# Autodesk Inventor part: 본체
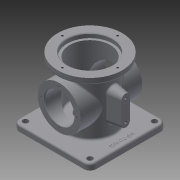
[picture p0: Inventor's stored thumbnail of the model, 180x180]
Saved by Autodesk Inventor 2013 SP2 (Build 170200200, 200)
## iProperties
Created: 2017-08
Part Number: 본체
Material: 일반
Document SubType Name: Modeling
Designer: mduedu
Density: 1 g/cm^3
Mass: 872.327 g
Surface Area: 642.238 cm^2
Volume: 321.892 cm^3
Author: mduedu
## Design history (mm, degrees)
sketch "스케치1"
  geometry: L1 (-62.5, -62.5)-(62.5, -62.5); L2 (62.5, -62.5)-(62.5, 62.5); L3 (62.5, 62.5)-(-62.5, 62.5); L4 (-62.5, 62.5)-(-62.5, -62.5); L5 (-62.5, -62.5)-(62.5, 62.5); L6 (62.5, -62.5)-(-62.5, 62.5); 1 further point
  constraints: 12 end point, 2 midpoint, 2 parallel, 1 horizontal, 1 perpendicular
  dimensions: "d232" = 125 distance of L3.end L2.end; "d233" = 125 distance of L2.end L1.end
extrude "돌출1" new body sketch "스케치1" distance "d5" = 10; taper "d6" = 0 deg
sketch "스케치2"
  geometry: C1 r 38 at (0, 0); 1 further point
  constraints: 1 centre point, 1 coincident
  dimensions: "d111" = 76 diameter of C1
extrude "돌출2" join sketch "스케치2" distance "d12" = 88; taper "d13" = 0 deg
sketch "스케치3"
  geometry: C1 r 52.5 at (0, 0); 1 further point
  constraints: 1 centre point, 1 coincident
  dimensions: "d114" = 105 diameter of C1
extrude "돌출3" join sketch "스케치3" distance "d19" = 10; taper "d20" = 0 deg
sketch "스케치4"
  geometry: C1 r 33 at (0, 0); 1 further point
  constraints: 1 centre point, 1 coincident
  dimensions: "d115" = 66 diameter of C1
extrude "돌출4" cut sketch "스케치4" distance "d26" = 86; taper "d27" = 0 deg
sketch "스케치5"
  geometry: C1 r 37 at (0, 0); 1 further point
  constraints: 1 centre point, 1 coincident
  dimensions: "d116" = 74 diameter of C1
extrude "돌출5" cut sketch "스케치5" distance "d29" = 7; taper "d30" = 0 deg
node "작업 평면1"
sketch "스케치18"
  geometry: L1 (-62.5, 0)-(62.5, 0) reference; C1 r 35 at (0, 54); 1 further point
  constraints: 1 centre point, 1 vertical alignment
  dimensions: "d118" = 70 diameter of C1; "d234" = 54 distance from line of C1.centre L1
extrude "돌출9" join sketch "스케치18" stored distance "d120" = 10; taper "d121" = 0 deg
hole "구멍8" diameter "d124" = 48; stored, may be unused: countersink angle "d128" = 90 deg, drill point angle "d130" = 118 deg; dims "d122" = 10, "d123" = 10, "d125" = 6, "d126" = 4, "d127" = 2, "d129" = 8
sketch "스케치9"
  geometry: C1 r 33 at (0, 0); 1 further point
  constraints: 1 centre point, 1 coincident
  dimensions: "d131" = 66 diameter of C1
extrude "돌출8" cut sketch "스케치9" distance "d43" = 16; taper "d44" = 0 deg
node "작업 평면2"
fillet "모깎기9" dims "d137" = 3
fillet "모깎기10" dims "d138" = 3
chamfer "모따기2" distance "d139" = 1; stored, may be unused: second distance "d140" = 2, angle "d141" = 45 deg
fillet "모깎기11" dims "d142" = 3
fillet "모깎기12" dims "d143" = 3
fillet "모깎기13" dims "d144" = 3
node "작업 평면3"
sketch "스케치20"
  geometry: L1 (108, -52.5)-(108, 52.5) reference; L2 (37, 7)-(71, 7); L3 (37, -7)-(71, -7); L4 (0, -33)-(0, 33) reference; A1 r 7 centre (37, 0) between (37, 7) and (37, -7); A2 r 7 centre (71, 0) between (71, 7) and (71, -7); 1 further point
  constraints: 4 end point, 4 point on circle, 3 tangent, 2 centre point, 2 horizontal alignment, 1 parallel, 1 perpendicular
  dimensions: "d203" = 14 diameter of A1; "d206" = 30 distance edge to line of A2 L1; "d207" = 48 dimension on A2 A1 (derived); "d236" = 30 distance edge to line of A1 L4
extrude "돌출10" join sketch "스케치20" stored distance "d152" = 10; taper "d153" = 10 deg
sketch "스케치21"
  geometry: C1 r 7 at (0, 71) reference; C2 r 7 at (0, 37) reference; 3 further points
  constraints: 2 coincident
hole "구멍12" sketch "스케치21" at (0, 71), (0, 37) diameter "d219" = 4.134; stored, may be unused: countersink angle "d223" = 90 deg, drill point angle "d225" = 118 deg; dims "d220" = 6, "d221" = 4, "d222" = 2, "d224" = 8
fillet "모깎기18" dims "d229" = 3
sketch "스케치23"
  geometry: C1 r 20 at (0, 0); 1 further point
  constraints: 1 centre point, 1 coincident
  dimensions: "d168" = 40 diameter of C1
extrude "돌출12" cut sketch "스케치23" stored distance "d169" = 148.25; taper "d170" = 0 deg
sketch "스케치28"
  geometry: L1 (62.5, -62.5)-(62.5, 62.5) reference; 2 further points
  constraints: 1 horizontal alignment, 1 other
  dimensions: "d238" = 10 distance from line of point (52.5, 0) L1
feature "엠보싱4" sketch "스케치28" dims "d239" = 0.5, "d240" = 0
sketch "스케치25" dims "d178" = 58
  geometry: C1 r 35 at (0, 0) reference; 3 further points
  constraints: 2 vertical alignment, 1 coincident, 2 other
hole "구멍10" sketch "스케치25" at (0, 29) diameter "d179" = 3.242; stored, may be unused: countersink angle "d183" = 90 deg, drill point angle "d185" = 118 deg; dims "d180" = 4, "d181" = 4, "d182" = 2, "d184" = 6
sketch "스케치26" dims "d189" = 90
  geometry: 3 further points
  constraints: 2 vertical alignment, 1 coincident, 2 other
hole "구멍11" sketch "스케치26" at (0, 45) diameter "d190" = 3.242; stored, may be unused: countersink angle "d194" = 90 deg, drill point angle "d196" = 118 deg; dims "d191" = 4, "d192" = 4, "d193" = 2, "d195" = 6
chamfer "모따기4" distance "d200" = 1; stored, may be unused: second distance "d201" = 2, angle "d202" = 45 deg
fillet "모깎기19" dims "d241" = 10
sketch "스케치29"
  geometry: A1 r 10 centre (-52.5, 52.5) between (-52.5, 62.5) and (-62.5, 52.5) reference; A2 r 10 centre (52.5, 52.5) between (62.5, 52.5) and (52.5, 62.5) reference; A3 r 10 centre (52.5, -52.5) between (52.5, -62.5) and (62.5, -52.5) reference; A4 r 10 centre (-52.5, -52.5) between (-62.5, -52.5) and (-52.5, -62.5) reference; 5 further points
  constraints: 4 coincident
hole "구멍13" sketch "스케치29" at (-52.5, 52.5), (52.5, 52.5), (52.5, -52.5), (-52.5, -52.5) diameter "d242" = 9; stored, may be unused: countersink angle "d246" = 90 deg, drill point angle "d248" = 118 deg; dims "d243" = 6, "d244" = 4, "d245" = 2, "d247" = 8
fillet "모깎기20" dims "d249" = 3
node "솔리드1"
mirror "대칭2"
pattern_circular "원형 패턴1" dims angle "d187" = 360 deg
mirror "대칭3"
pattern_circular "원형 패턴2" dims angle "d198" = 360 deg
other parameters: "d147" = 58
